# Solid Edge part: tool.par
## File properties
Author: Mac
Template: Normal.par
Last saved by: Mac
Revision: 1
Application: Solid Edge
Density: 1024,000 kg/m^3
Accuracy: 0,990
Material: ABS Plastic, medium impact
Face Style: Black
Fill Style: ANSI34(Plastic)
Virtual Style: Black (Shiny)
Coef. of Thermal Exp: 5.8e-05
Thermal Conductivity: 2.0
Specific Heat: 0.0
Modulus of Elasticity: 2275269810.0
Poission's Ratio: 0.4
Yield Stress: 43436969.1
Ultimate Stress: 0.0
Elongation: 0.0
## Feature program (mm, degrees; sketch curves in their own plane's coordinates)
swept protrusion "unnamed SweptProtrusion 1"
sketch for "ExtrudedCutout_1" plane through (7.6047, 0, 2.1729) normal (0.96152, 0, 0.274735) x-axis (0, 1, 0)
  bspline degree 3 poles (-4.0027, 6.841) (-3.9987, 8.0032) (-2.2481, 8.0011) (0, 8.0014) knots 0 1 multiplicities 4 4
  bspline degree 3 poles (4.0027, 6.841) (3.9987, 8.0032) (2.2481, 8.0011) (0, 8.0014) knots 0 1 multiplicities 4 4
extrude "ExtrudedCutout_1" cut finite 15.6 symmetric
fillet "Round_1" radius 0.06
sketch for "unnamed Cutout 1" plane through (-0.96, -1.5157, 7.9993) normal (0.005997, 0, 0.999982) x-axis (0.999982, 0, -0.005997)
  bspline degree 3 poles (6.9284, -2.487) (8.2924, -2.4911) (8.7303, -1.4216) (8.7559, 1.5157) knots 0 1 multiplicities 4 4
  bspline degree 3 poles (6.9284, 5.5184) (8.2924, 5.5226) (8.7303, 4.453) (8.7559, 1.5157) knots 0 1 multiplicities 4 4
extrude "unnamed Cutout 1" cut through along -normal
fillet "Round_2" radius 0.06
sketch for "ExtrudedCutout_3" plane through (1.1551, -3.9273, 2.2041) normal (-0.546517, -0.000121, -0.837448) x-axis (-0.000122, 1, -6.5e-05)
extrude "ExtrudedCutout_3" cut finite 4.6 along +normal
fillet "Round_3" radius 0.08
sketch for "ExtrudedProtrusion_2" #1 plane through (3.7447, 2.2001, 0.3) normal (0, 0, -1) x-axis (1, 0, 0)
  line (2.877, 4.1003) -> (-2.8591, 4.1003)
  line (-2.8591, 4.1003) -> (-2.8591, 4.7003)
  line (-2.8591, 4.7003) -> (2.877, 4.7003)
  line (2.877, 4.7003) -> (2.877, 4.1003)
sketch for "ExtrudedProtrusion_2" #2 plane through (3.7447, 2.2001, 0.3) normal (0, 0, -1) x-axis (1, 0, 0)
  line (2.877, 0.3) -> (-2.8591, 0.3)
  line (-2.8591, 0.3) -> (-2.8591, -0.3)
  line (-2.8591, -0.3) -> (2.877, -0.3)
  line (2.877, -0.3) -> (2.877, 0.3)
extrude "ExtrudedProtrusion_2" add finite 0.1 along -normal
sketch for "unnamed Cutout 2" #1 plane through (0.8856, 2.2001, 0.35) normal (-1, 0, 0) x-axis (0, -1, 0)
  line (-0.5125, 0.1487) -> (0.4923, 0.1487)
  line (0.4923, 0.1487) -> (0.4923, -0.2247)
  line (0.4923, -0.2247) -> (-0.5125, -0.2247)
  line (-0.5125, -0.2247) -> (-0.5125, 0.1487)
sketch for "unnamed Cutout 2" #2 plane through (0.8856, 2.2001, 0.35) normal (-1, 0, 0) x-axis (0, -1, 0)
  line (4.7001, 0.03) -> (4.7001, -0.05)
  line (4.1001, -0.05) -> (4.7001, -0.05)
  line (4.1001, 0.03) -> (4.1001, -0.05)
  arc centre (4.1201, 0.03) radius 0.02 from (4.1401, 0.03) to (4.1001, 0.03) ccw
  line (4.1401, 0) -> (4.1401, 0.03)
  arc centre (4.1501, 0) radius 0.01 from (4.1501, -0.01) to (4.1401, 0) cw
  line (4.6501, -0.01) -> (4.1501, -0.01)
  arc centre (4.6501, 0) radius 0.01 from (4.6601, 0) to (4.6501, -0.01) cw
  line (4.6601, 0.03) -> (4.6601, 0)
  arc centre (4.6801, 0.03) radius 0.02 from (4.7001, 0.03) to (4.6601, 0.03) ccw
sketch for "unnamed Cutout 2" #3 plane through (0.8856, 2.2001, 0.35) normal (-1, 0, 0) x-axis (0, -1, 0)
  line (4.9126, 0.1487) -> (3.9078, 0.1487)
  line (3.9078, 0.1487) -> (3.9078, -0.2247)
  line (3.9078, -0.2247) -> (4.9126, -0.2247)
  line (4.9126, -0.2247) -> (4.9126, 0.1487)
sketch for "unnamed Cutout 2" #4 plane through (0.8856, 2.2001, 0.35) normal (-1, 0, 0) x-axis (0, -1, 0)
  line (-0.3, 0.03) -> (-0.3, -0.05)
  line (0.3, -0.05) -> (-0.3, -0.05)
  line (0.3, 0.03) -> (0.3, -0.05)
  line (0.26, 0) -> (0.26, 0.03)
  arc centre (0.25, 0) radius 0.01 from (0.25, -0.01) to (0.26, 0) ccw
  line (-0.25, -0.01) -> (0.25, -0.01)
  arc centre (-0.25, 0) radius 0.01 from (-0.26, 0) to (-0.25, -0.01) ccw
  line (-0.26, 0.03) -> (-0.26, 0)
extrude "unnamed Cutout 2" cut through along -normal
sketch for "ExtrudedProtrusion_1" #1 plane through (0, 0, 0.3) normal (0, 0, 1) x-axis (1, 0, 0)
  circle centre (1.7959, 2.2001) radius 0.25
sketch for "ExtrudedProtrusion_1" #2 plane through (0, 0, 0.3) normal (0, 0, 1) x-axis (1, 0, 0)
  circle centre (5.6939, 2.2001) radius 0.25
sketch for "ExtrudedProtrusion_1" #3 plane through (0, 0, 0.3) normal (0, 0, 1) x-axis (1, 0, 0)
  circle centre (5.6939, -2.1999) radius 0.25
sketch for "ExtrudedProtrusion_1" #4 plane through (0, 0, 0.3) normal (0, 0, 1) x-axis (1, 0, 0)
  circle centre (1.7959, -2.1946) radius 0.25
extrude "ExtrudedProtrusion_1" add along +normal  Profile_Plane1_Distance = 0.3 mm
fillet "Round_5" radius 0.1
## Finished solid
Body 1: solid body, 76 faces, 182 edges, 107 vertices.
  Faces by surface: plane 25, blend 21, cylinder 12, spline 11, swept 5, torus 2
  Edges by curve: intersection 68, line 53, circle 38, curve on surface 16, spline 7
Bounding box of the edges (mm; curved faces can reach further): 9.033 x 8.005 x 7.700, from (-1.2757, -4.0027, 0.3) to (7.7574, 4.0027, 8.0003).
Cylindrical faces by radius (mm): R0.01 x4, R0.02 x4, R0.25 x4
Toroidal faces (ring radius, tube radius in mm): R0.3462 r0.1001 x1, R0.3473 r0.1001 x1
Planar faces by outward normal: +x 2, +y 4, +z 4, -x 2, -y 4, -z 6, oblique 3
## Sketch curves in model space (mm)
spline (1.2395, 0, 0.4561) -> (4.5841, 0, 0.6386) -> (7.8223, 0, 1.4113)
arc centre (1.3763, 0, 2.3214) radius 1.8703 from (-0.2761, 0, 1.4451) through (0.3541, 0, 0.7551) to (1.2395, 0, 0.4561)
spline (-0.2761, 0, 1.4451) -> (-1.0685, 0, 4.1532) -> (-1.3103, 0, 8.0014)
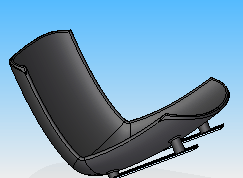
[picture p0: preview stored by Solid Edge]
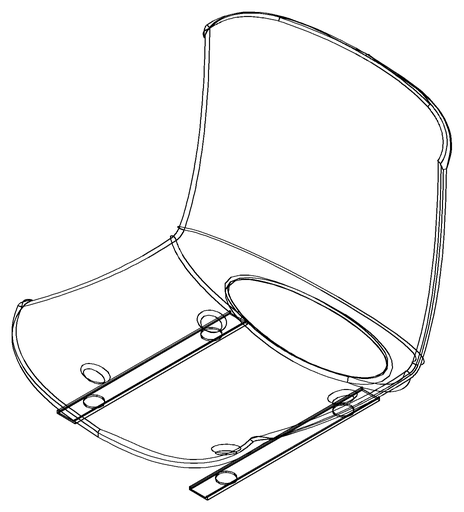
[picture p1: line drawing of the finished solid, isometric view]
